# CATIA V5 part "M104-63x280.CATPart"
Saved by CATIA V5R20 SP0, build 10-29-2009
Part number: M104-63x280
Source: Unknown
Bounding box of the stored display mesh (mm): x -31.459 to 31.459, y -31.459 to 31.459, z 0 to 280
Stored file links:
  C:\Users\Utente\Desktop\IO LAVORO\3D X SITO CF\X SITO\M104\M104-63x280.CATPart
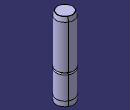
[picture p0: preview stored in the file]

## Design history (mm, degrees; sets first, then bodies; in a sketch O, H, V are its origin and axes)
Body1 (main body)
  Solid1 "PartBody": solid without history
